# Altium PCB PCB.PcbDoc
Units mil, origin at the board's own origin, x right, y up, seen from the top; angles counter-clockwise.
Board outline 4950 x 3450 mil, 2 copper layers (Top Layer, Bottom Layer), stack 62 mil thick; 23 components, 0 nets, 11 pads, 0 vias.
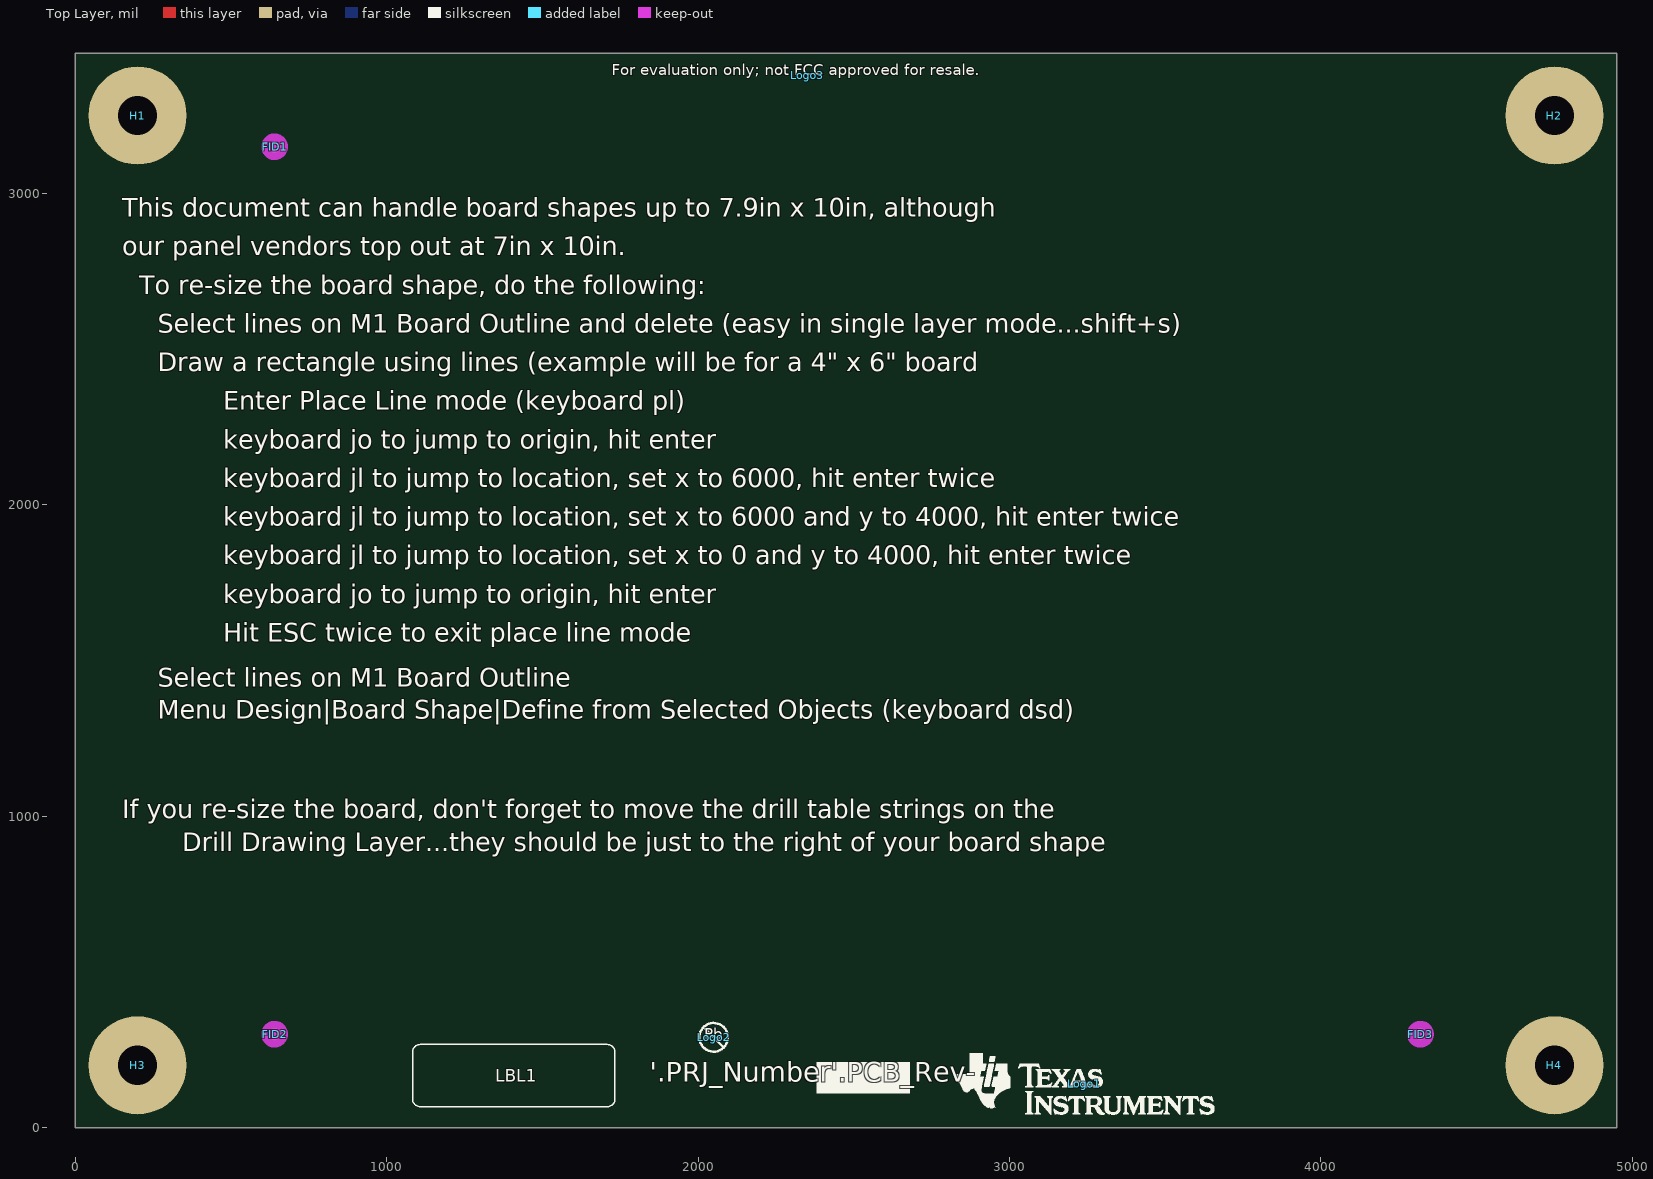
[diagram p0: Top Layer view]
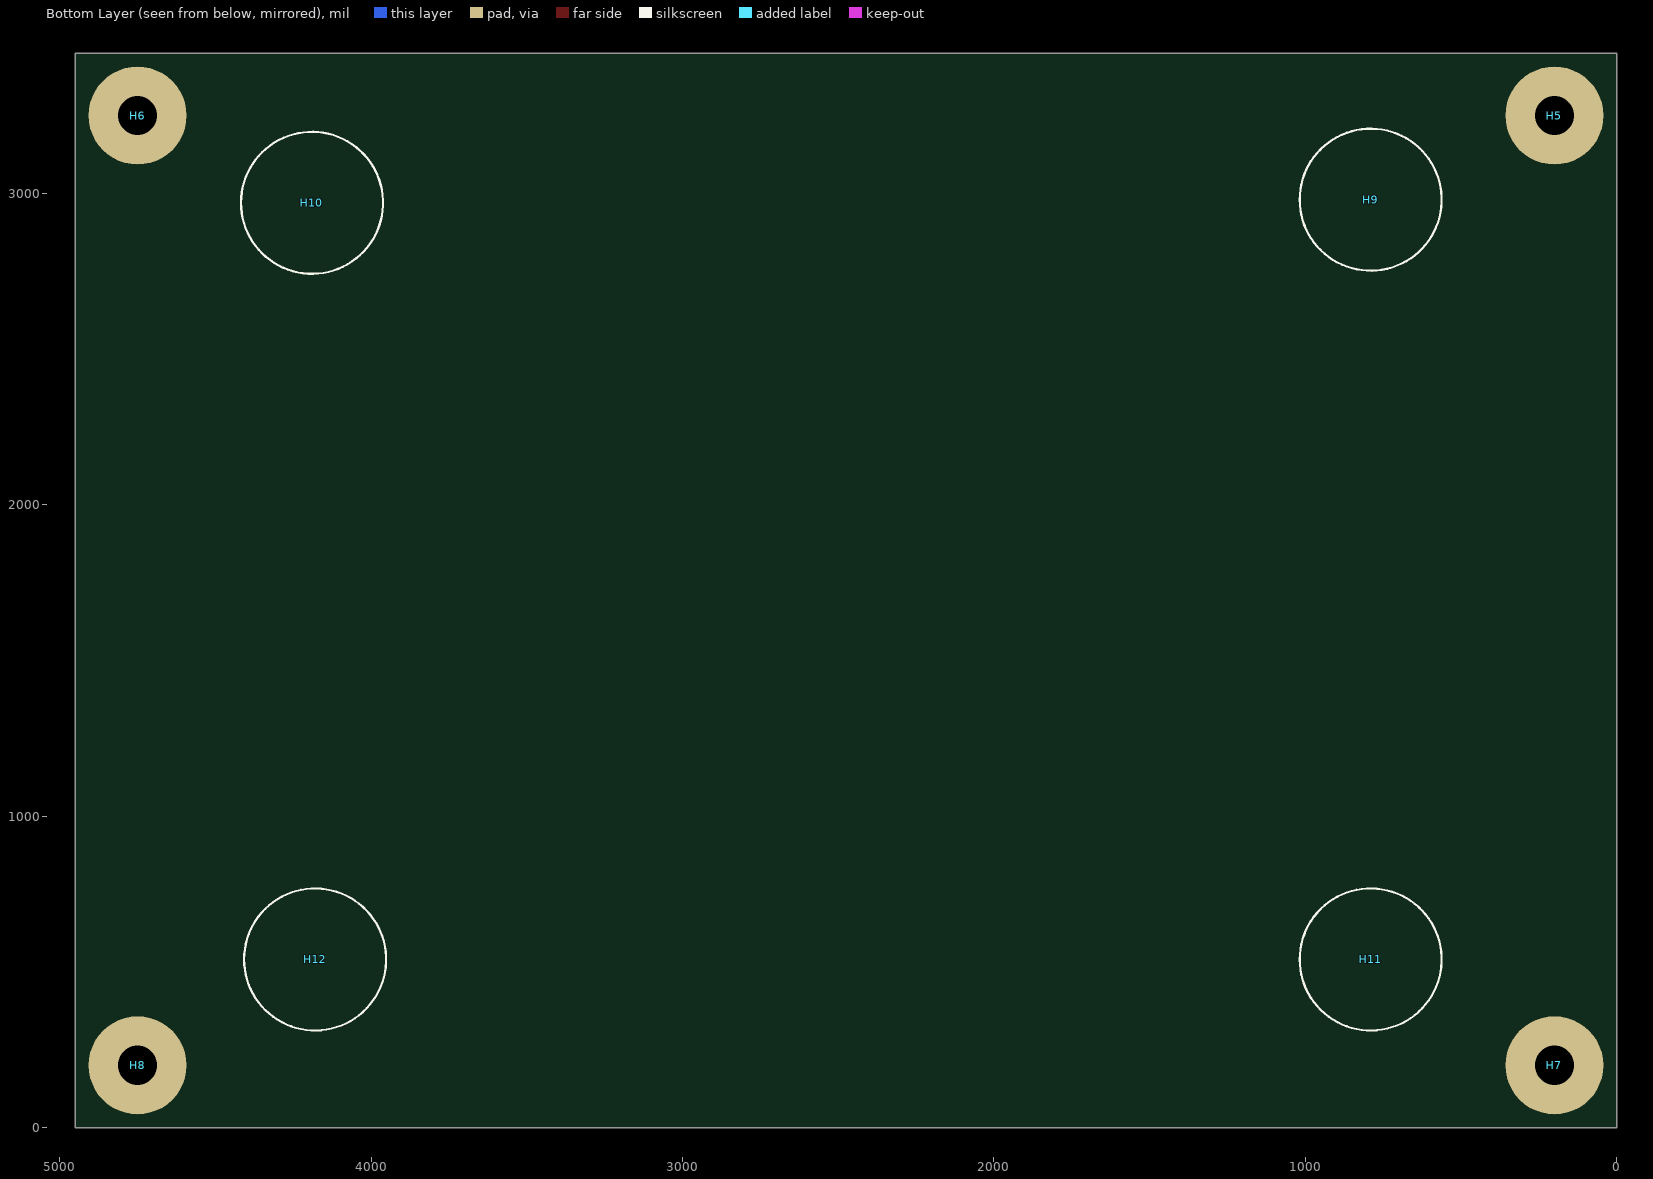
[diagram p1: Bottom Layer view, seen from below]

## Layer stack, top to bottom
Top Solder: solder mask 0.4, Solder Resist, Dk 3.5
Top Layer: signal copper 1.4
Dielectric1: core 59.2, FR-4, Dk 4.8
Bottom Layer: signal copper 1.4
Bottom Solder: solder mask 0.4, Solder Resist, Dk 3.5

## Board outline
0,0 4950,0 4950,3450 0,3450

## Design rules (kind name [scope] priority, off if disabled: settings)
AcuteAngle [All] p1: minimum=4.50000000000000E+0001 checktracksonly=FALSE
AssemblyTestPointUsage [All] p1: valid=2
BoardOutlineClearance BoardOutlineClearance_MountingHoles [OnCopper and InComponentClass('Mounting Holes')] p1: gap=40 ignorepadtopadclearanceinfootprint=FALSE
BoardOutlineClearance BoardOutlineClearance_Poly [OnCopper and IsPoly] p2: gap=25 ignorepadtopadclearanceinfootprint=FALSE
BoardOutlineClearance [OnCopper and Not InComponentClass('Logo') and not InComponentClass('FiducialMark') and not InRegion(1000,500,4000,800) and not InPoly] p3: gap=75 ignorepadtopadclearanceinfootprint=FALSE
Clearance Clearance_Keepouts [((IsTrack Or IsArc) And Not InPoly) And IsFree and IsKeepOut vs ((IsTrack Or IsArc) And Not InPoly) And IsFree and IsKeepOut] p1: gap=0 ignorepadtopadclearanceinfootprint=FALSE
Clearance Clearance_Poly [InPolygon] p2: gap=25 ignorepadtopadclearanceinfootprint=FALSE except(0: Arc-Hole Track-Hole SMDPad-Hole THPad-Hole Via-Hole Fill-Hole Poly-Hole Region-Hole Text-Hole)
Clearance Clearance_FiducialMark [IsKeepOut and InComponentClass('FiducialMark') vs IsPad and InComponentClass('FiducialMark')] p3: gap=0 ignorepadtopadclearanceinfootprint=FALSE
Clearance [All] p4: gap=7.87 ignorepadtopadclearanceinfootprint=FALSE except(0: Arc-Hole Track-Hole SMDPad-Hole THPad-Hole Via-Hole Fill-Hole Poly-Hole Region-Hole Text-Hole)
ComponentClearance ComponentClearance_MountingHoles_FiducialMarks [InComponentClass('Mounting Holes') vs InComponentClass('FiducialMark')] p1: gap=50 collisioncheckmode=3 verticalgap=10 showdistances=FALSE
ComponentClearance ComponentClearance_Shunt [InComponentClass('Header') vs InComponentClass('Shunt')] p2: gap=0 collisioncheckmode=3 verticalgap=0 showdistances=FALSE
ComponentClearance ComponentClearance_Logo [InComponentClass('Logo')] p3: gap=50 collisioncheckmode=3 verticalgap=10 showdistances=FALSE
ComponentClearance ComponentClearance_ScrewToNut [(HasFootprint('NY PMS 440 0025 PH')) vs (HasFootprint('Keystone_1902C'))] p4: gap=5 collisioncheckmode=3 verticalgap=10 showdistances=FALSE
ComponentClearance ComponentClearance_MountingHoles [InComponentClass('Mounting Holes')] p5: gap=250 collisioncheckmode=3 verticalgap=100000 showdistances=FALSE
ComponentClearance ComponentClearance_SmallPassives [HasFootprint('0201*') or HasFootprint('0402*') or HasFootprint('0508') or HasFootprint('0603*') or HasFootprint('0612') or HasFootprint('0805*') or HasFootprint('0815*') or HasFootprint('0830*') or HasFootprint('1206*') or HasFootprint('1210*') or HasFootprint('1808*') or HasFootprint('1812*') or HasFootprint('1825*') or HasFootprint('2010*') or HasFootprint('2220*') or HasFootprint('2225*') or HasFootprint('2512*') or HasFootprint('2728*') or HasFootprint('3518*') vs HasFootprint('0201*') or HasFootprint('0402*') or HasFootprint('0508') or HasFootprint('0603*') or HasFootprint('0612') or HasFootprint('0805*') or HasFootprint('0815*') or HasFootprint('0830*') or HasFootprint('1206*') or HasFootprint('1210*') or HasFootprint('1808*') or HasFootprint('1812*') or HasFootprint('1825*') or HasFootprint('2010*') or HasFootprint('2220*') or HasFootprint('2225*') or HasFootprint('2512*') or HasFootprint('2728*') or HasFootprint('3518*')] p6: gap=14.96 collisioncheckmode=3 verticalgap=10 showdistances=FALSE
ComponentClearance ComponentClearance_THtoSMT [IsThruComponent vs IsSMTComponent] p7: gap=40 collisioncheckmode=3 verticalgap=30 showdistances=FALSE
ComponentClearance ComponentClearance_THtoTH [IsThruComponent vs IsThruComponent] p8: gap=30 collisioncheckmode=3 verticalgap=30 showdistances=FALSE
ComponentClearance [All] p9: gap=30 collisioncheckmode=3 verticalgap=10 showdistances=FALSE
DiffPairsRouting [All] p1: maxlimit=100 minlimit=10 mostfreqgap=10 toplayer_minwidth=15 toplayer_maxwidth=15 toplayer_prefwidth=15 bottomlayer_minwidth=15 bottomlayer_maxwidth=15 bottomlayer_prefwidth=15 maxuncoupledlength=1000
FabricationTestPointUsage TestPointUsage [All] p1: valid=2 allowmultiple=FALSE
FabricationTestpoint Testpoint [All] p1: side=3 testpointundercomponent=TRUE minsize=40 maxsize=100 preferedsize=60 minholesize=0 maxholesize=40 preferedholesize=32 testpointgrid=1 allowsidetop=TRUE allowsidebottom=TRUE usegrid=TRUE gridtolerance=0.01
FanoutControl Fanout_LCC [IsLCC] p1: bgadir=Out bgaviamode=Centered fanoutstyle=Auto fanoutdirection=Alternating viagrid=1 // Fanout_LCC (Default Rule)
FanoutControl Fanout_BGA [IsBGA] p2: bgadir=Out bgaviamode=Centered fanoutstyle=Auto fanoutdirection=Alternating viagrid=1 // Fanout_BGA (Default Rule)
FanoutControl Fanout_Default [All] p4: bgadir=Out bgaviamode=Centered fanoutstyle=Auto fanoutdirection=Alternating viagrid=1 // Fanout_Default (Default Rule)
FanoutControl Fanout_Small [(CompPinCount < 5)] p5: bgadir=Out bgaviamode=Centered fanoutstyle=Auto fanoutdirection=OutThenIn viagrid=1 // Fanout_Small (Default Rule)
HoleSize [All] p1: absolutevalues=TRUE maxlimit=251 minlimit=7.87 maxpercent=80.000 minpercent=20.000
MinimumAnnularRing MinimumAnnularRing_ThermalPadVias [IsVia and InAnyComponent] p1: minimumring=5.91
MinimumAnnularRing [All] p2: minimumring=8
MinimumSolderMaskSliver MinimumSolderMaskSliver_Logo [InComponentClass('Logo') vs InComponentClass('Logo')] p1: minsoldermaskwidth=0.7
MinimumSolderMaskSliver [All] p2: minsoldermaskwidth=3.94
PlaneConnect [All] p1: planeconnectstyle=Relief reliefexpansion=10 reliefentries=4 reliefconductorwidth=10 reliefairgap=10
PolygonConnect [All] p1: connectstyle=Relief reliefconductorwidth=10 reliefentries=4 polygonreliefangle="90 Angle" airgapwidth=10
RoutingVias ThermalPadVias [IsVia and InAnyComponent] p1: holewidth=7.87 width=19.68 viastyle="Through Hole" minholewidth=7.87 minwidth=19.68 maxholewidth=12.99 maxwidth=23.62
RoutingVias [All] p2: holewidth=16 width=34 viastyle="Through Hole" minholewidth=7.87 minwidth=26 maxholewidth=40 maxwidth=65
SilkToBoardRegionClearance [Not ((IsComment or IsDesignator) And (Hide <> 'False')) and not InRegion(1000,500,4000,800)] p1:
SilkToSilkClearance SilkToSilkClearance_Pb-FreeLogo [(HasFootprint('Pb-Free_Overlay_Medium') OR HasFootprint('Pb-Free_Overlay_Small')) vs (HasFootprint('Pb-Free_Overlay_Medium') OR HasFootprint('Pb-Free_Overlay_Small'))] p1: silktosilkclearance=0
SilkToSilkClearance [All] p2: silktosilkclearance=4
SilkToSolderMaskClearance SilkToComponentPadClearance [(IsPad or IsFill or IsRegion) and InAnycomponent] p1: minsilkscreentomaskgap=5 clearancetoexposedcopper=TRUE
SilkToSolderMaskClearance "Silk to Solder Mask Opening" [All] p2: minsilkscreentomaskgap=4 clearancetoexposedcopper=FALSE
SolderMaskExpansion [All] p1: expansion=1.97
Width [All] p1: maxlimit=100 minlimit=6 preferedwidth=10 checkconnectedcopper=TRUE
15 further rules are at their usual default settings.

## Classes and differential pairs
component class Label: LBL1
component class AssemblyNote: ZZ1 ZZ2 ZZ3 ZZ4
component class FiducialMark: FID1 FID2 FID3
component class Logo: Logo1
component class "Mounting Holes": H1 H2 H3 H4

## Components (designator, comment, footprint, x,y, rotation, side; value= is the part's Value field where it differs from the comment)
FID1 "Fiducial" Fiducial10-20 640,3150 r0 top
FID2 "Fiducial" Fiducial10-20 640,300 r0 top
FID3 "Fiducial" Fiducial10-20 4320,300 r0 top
H1 "NY PMS 440 0025 PH" "NY PMS 440 0025 PH" 200,3250 r0 top locked
H2 "NY PMS 440 0025 PH" "NY PMS 440 0025 PH" 4750,3250 r0 top locked
H3 "NY PMS 440 0025 PH" "NY PMS 440 0025 PH" 200,200 r0 top locked
H4 "NY PMS 440 0025 PH" "NY PMS 440 0025 PH" 4750,200 r0 top locked
H5 "1902C" Keystone_1902C 200,3250 r180 bottom locked
H6 "1902C" Keystone_1902C 4750,3250 r180 bottom locked
H7 "1902C" Keystone_1902C 200,200 r180 bottom locked
H8 "1902C" Keystone_1902C 4750,200 r180 bottom locked
H9 "SJ-5303 (CLEAR)" Bumpon_SJ5003Transparent 790,2980 r180 bottom
H10 "SJ-5303 (CLEAR)" Bumpon_SJ5003Transparent 4190,2970 r180 bottom
H11 "SJ-5303 (CLEAR)" Bumpon_SJ5003Transparent 790,540 r180 bottom
H12 "SJ-5303 (CLEAR)" Bumpon_SJ5003Transparent 4180,540 r180 bottom
LBL1 "Size: 0.65\" x 0.20 \"" Label_650x200 1408,167 r0 top
Logo1 "Texas Instruments" TI_Stacked_Overlay_Small 3240,140 r0 top
Logo2 "Pb-Free Symbol" Pb-Free_Overlay_Small 2050,290 r0 top
Logo3 "FCC disclaimer" FCC_disclaimer 2350,3380 r0 top
ZZ1 "This Assembly Note is for PCB labels only" AssemblyNoteLabel 185,3938 r0 top
ZZ2 "These assemblies are ESD sensitive, ESD precautions shall be observed." AssemblyNote 185,3829.11 r0 top
ZZ3 "These assemblies must be clean and free from flux and all contaminants. Use of no clean flux is not acceptable." AssemblyNote 185,3740.56 r0 top
ZZ4 "These assemblies must comply with workmanship standards IPC-A-610 Class 2, unless otherwise specified." AssemblyNote 185,3652 r0 top

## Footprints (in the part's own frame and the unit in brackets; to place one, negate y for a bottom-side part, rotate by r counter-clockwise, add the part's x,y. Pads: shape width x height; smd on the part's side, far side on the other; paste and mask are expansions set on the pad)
AssemblyNote [mil] "Assembly Note"
AssemblyNoteLabel [mil] "Assembly Note for PCB Labels"
Bumpon_SJ5003Transparent [mil] "3M Hemispherical Bumpon transparent"
  round 1 on Mech4: 0(0,0)
  silkscreen extent -228,-228 228,228, body extent -219,-219 219,219, height 197
FCC_disclaimer [mil]
Fiducial10-20 [mm]
  round 1 smd mask+0.5: 1(0,0)
  Top Layer keep-out circle w1.178: c0,0 r0.5
Keystone_1902C [mil] "Hex Standoff, 4-40 threaded, nylon"
  body extent -145,-126 146,126, height 501
Label_650x200 [mil] "Thermal Transfer Label"
  silkscreen extent -325,-100 325,100, body extent -325,-100 325,100, height 1
"NY PMS 440 0025 PH" [mm] "4-40 nylon screw and mounting hole"
  round 8 hole 3.2: 1(0,0)
  body extent -3.3,-3.3 3.3,3.3, height 2.69
Pb-Free_Overlay_Small [mil]
  silkscreen extent -46,-46 46,46
TI_Stacked_Overlay_Small [mil]
  silkscreen extent -418,-98 418,98

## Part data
FID1 FID2 FID3: "Fiducial mark.  There is nothing to buy or mount.", Manufacturer=N/A
H1 H2 H3 H4: "Machine Screw, Round, #4-40 x 1/4, Nylon, Philips panhead", DigiKeyPartNumber=H542-ND, Manufacturer="B&F Fastener Supply"
H5 H6 H7 H8: "Standoff, Hex, 0.5\"L #4-40 Nylon", Manufacturer=Keystone, Supplier Part Number 1=36-1902C-ND
H9 H10 H11 H12: "Bumpon, Hemisphere, 0.44 X 0.20, Clear", Manufacturer=3M, Supplier Part Number 1=SJ5303-7-ND
LBL1: library part THT-14-423-10, "Thermal Transfer Printable Labels, 0.650\" W x 0.200\" H - 10,000 per roll", Manufacturer=Brady, Supplier Part Number 1=97C5133
Logo1: library part TI_Logo, "Texas Instrument Corporate Signature"
Logo2: library part Pb-Free
Logo3: library part FCC_disclaimer, "FCC_disclaimer"
ZZ1: library part AssemblyNoteLabel
ZZ2 ZZ3 ZZ4: library part AssemblyNote

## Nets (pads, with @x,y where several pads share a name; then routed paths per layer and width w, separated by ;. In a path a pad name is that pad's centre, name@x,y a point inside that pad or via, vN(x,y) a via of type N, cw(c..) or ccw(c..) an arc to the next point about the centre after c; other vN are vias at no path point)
pads on no net: FID1.1 FID2.1 FID3.1 H1.1 H2.1 H3.1 H4.1 H9.0 H10.0 H11.0 H12.0

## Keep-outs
Keep-Out Layer:
  text ".Layer_Name" at 577,-858.49 h60

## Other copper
Top Layer:
  text ".Layer_Name" at 577,-858.49 h60
Bottom Layer:
  text ".Layer_Name" at 577,-858.49 h60

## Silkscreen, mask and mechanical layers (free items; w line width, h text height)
Top Overlay:
  region: 2680,210 2380,210 2380,110 2680,110
  text "This document can handle board shapes up to 7.9in x 10in, although" at 150,2925 h60
  text "our panel vendors top out at 7in x 10in." at 150,2800.94 h60
  text "To re-size the board shape, do the following:" at 205,2676.88 h60
  text "Select lines on M1 Board Outline and delete (easy in single layer mode...shift+s)" at 265,2552.82 h60
  text "Draw a rectangle using lines (example will be for a 4\" x 6\" board" at 265,2428.76 h60
  text "Enter Place Line mode (keyboard pl)" at 475,2304.71 h60
  text "keyboard jo to jump to origin, hit enter" at 475,2180.65 h60
  text "keyboard jl to jump to location, set x to 6000, hit enter twice" at 475,2056.59 h60
  text "keyboard jl to jump to location, set x to 6000 and y to 4000, hit enter twice" at 475,1932.53 h60
  text "keyboard jl to jump to location, set x to 0 and y to 4000, hit enter twice" at 475,1808.47 h60
  text "keyboard jo to jump to origin, hit enter" at 475,1684.41 h60
  text "Hit ESC twice to exit place line mode" at 475,1560.35 h60
  text "Select lines on M1 Board Outline" at 265,1416.3 h60
  text "Menu Design|Board Shape|Define from Selected Objects (keyboard dsd)" at 265,1312.24 h60
  text "If you re-size the board, don't forget to move the drill table strings on the" at 150,993 h60
  text "Drill Drawing Layer...they should be just to the right of your board shape" at 343,887 h60
  text "'.PRJ_Number'.PCB_Rev-" at 1845,125.77 h108.27
  text ".Layer_Name" at 577,-858.49 h60
Bottom Overlay:
  text ".Layer_Name" at 577,-858.49 h60
Top Paste:
  text ".Layer_Name" at 577,-858.49 h60
Bottom Paste:
  text ".Layer_Name" at 577,-858.49 h60
Top Solder:
  text ".Layer_Name" at 577,-858.49 h60
  text ".Layer_Name" at 577,-858.49 h60
Bottom Solder:
  text ".Layer_Name" at 577,-858.49 h60
Drill Guide:
  text ".Layer_Name" at 577,-858.49 h60
M1 Board Outline:
  the board outline again, w10
  text ".Layer_Name" at 577,-858.49 h60
M2 Board Dimensions:
  rectangle: 125,-400 500,-275
  rectangle: 0,-275 125,-150
  lines w7: 0,-275 1000,-275 ; 125,-400 125,-150 ; 250,-400 250,-150 ; 500,-400 500,-150 ; 750,-400 750,-150 ; 0,-400 0,-150 1000,-150 1000,-400 0,-400
  text ".Layer_Name" at 577,-858.49 h60
M3 3D STEP Top:
  text ".Layer_Name" at 577,-858.49 h60
M4 3D STEP Bottom:
  text ".Layer_Name" at 577,-858.49 h60
M5 Assembly Top:
  lines w10: -292,-930.17 6308,-930.17 ; -292,-726.83 6310,-726.83 ; -292,-523.5 -292,-1133.5 3713,-1133.5 6310,-1133.5 6310,-523.5 -291.5,-523.5 -291.5,-1133.5 1284,-1133.5 ; 2173,-1133.5 2173,-523.5 ; 3440,-726.83 3440,-523.5 ; 4280,-726.83 4280,-523.5 ; 4902,-1140 4902,-937.17
  text "COMPONENTS MARKED 'DNP' SHOULD NOT BE POPULATED." at 1153.5,-318.5 h60
  text "ASSEMBLY VARIANT:" at 1153,-434 h60
  text ".VariantName" at 2189,-434 h60
  text "PCB VIEWED FROM TOP SIDE" at -228.5,-655.67 h60
  text "BOARD #:" at 2248,-655.67 h60
  text ".PRJ_Number" at 2793.5,-655.67 h60
  text "REV:" at 3638,-655.67 h60
  text ".PCB_Rev" at 3929.5,-655.67 h60
  text "SVN REV:" at 4476,-655.67 h60
  text ".VersionControl_RevNumber" at 4982,-655.67 h60
  text "TID #:" at 2248,-859 h60
  text ".TID" at 2793.5,-859 h60
  text "PLOT NAME =" at -228.5,-1064.34 h60
  text ".plot_File_Name" at 577,-1064.34 h60
  text "GENERATED    :" at 2250,-1064.34 h60
  text ".Print_Date" at 3119.5,-1064.34 h60
  text ".Print_Time" at 3848.5,-1064.34 h60
  text "TEXAS INSTRUMENTS" at 5113,-1064.34 h60
M6 Assembly Bottom:
  lines w10: -292.5,-727.33 6309.5,-727.33 ; -290.5,-930.67 6309.5,-930.67 ; 1115.5,-1140.5 1115.5,-937.67 ; 1737.5,-727.33 1737.5,-524 ; 2577.5,-727.33 2577.5,-524 ; 3844.5,-1134 3844.5,-524 ; 4733.5,-1134 6309,-1134 6309,-524 -292.5,-524 -292.5,-1134 2304.5,-1134 6309.5,-1134 6309.5,-524
  text "COMPONENTS MARKED 'DNP' SHOULD NOT BE POPULATED." at 6102,-318 h60
  text ".VariantName" at 5058,-434 h60
  text "ASSEMBLY VARIANT:" at 6097,-434 h60
  text ".VersionControl_RevNumber" at 1035.5,-656.17 h60
  text "SVN REV:" at 1541.5,-656.17 h60
  text ".PCB_Rev" at 2088,-656.17 h60
  text "REV:" at 2379.5,-656.17 h60
  text ".PRJ_Number" at 3224,-656.17 h60
  text "BOARD #:" at 3769.5,-656.17 h60
  text "PCB VIEWED FROM BOTTOM SIDE" at 6246,-656.17 h60
  text ".TID" at 3224,-859.5 h60
  text "TID #:" at 3769.5,-859.5 h60
  text "TEXAS INSTRUMENTS" at 904.5,-1064.84 h60
  text ".Print_Time" at 2169,-1064.84 h60
  text ".Print_Date" at 2898,-1064.84 h60
  text "GENERATED    :" at 3767.5,-1064.84 h60
  text ".plot_File_Name" at 5440.5,-1064.84 h60
  text "PLOT NAME =" at 6246,-1064.84 h60
M9 Title Sheet:
  drawing of 57 lines, arcs and shapes, not listed
  text "1" at 739.84,8036.5 h70
  text "2" at 3235.5,8036.5 h70
  text "3" at 5724.84,8036.5 h70
  text "4" at 8231.51,8036.5 h70
  text "5" at 10730.5,8036.5 h70
  text "6" at 13235.5,8036.5 h70
  text "A" at -416.5,6893.5 h70
  text "A" at 14383.5,6893.5 h70
  text "B" at -416.5,4513.5 h70
  text "B" at 14383.5,4513.5 h70
  text "C" at -416.5,2138.5 h70
  text "C" at 14383.5,2138.5 h70
  text "PROJECT TITLE:" at 11343.5,277.5 h45
  text ".PRJ_Title" at 11393.5,144.17 h70
  text "DESIGNED FOR:" at 11343.5,-23.5 h45
  text ".PRJ_Customer" at 11393.5,-163.5 h70
  text "D" at -416.5,-231.5 h70
  text "D" at 14383.5,-231.5 h70
  text "FILE NAME:" at 11343.5,-323.5 h45
  text ".PCB_File_Name_No_Path" at 11393.5,-443.5 h70
  text "Texas Instruments (TI) and/or its licensors do not warrant the accuracy or completeness of this specification" at 6374,-605.34 h45
  text "ENGINEER:" at 11343.5,-613.5 h45
  text "LAYOUT BY:" at 12848.5,-613.5 h45
  text "or any information contained therein. TI and/or its licensors do not warrant that this design will meet" at 6329.01,-718 h45
  text ".PRJ_Engineer" at 11393.5,-768.49 h70
  text ".PCB_Layout" at 12899,-768.49 h70
  text "the specifications, will be suitable for your application or fit for any particular purpose, or will operate in" at 6329.01,-830.67 h45
  text ".Layer_Name" at 577,-858.49 h60
  text "ALTIUM DESIGNER VERSION:" at 12848.5,-923.5 h45
  text "an implementation. TI and/or its licensors do not warrant that the design is production worthy. You should" at 6329.01,-943.33 h45
  text "completely validate and test your design implementation to confirm the system functionality for your application." at 6374,-1056 h45
  text ".print_Scale" at 11393.5,-1056.83 h70
  text ".Application_BuildNumber" at 12899,-1056.83 h70
  text "1" at 739.84,-1263.5 h70
  text "2" at 3235.5,-1263.5 h70
  text "3" at 5724.84,-1263.5 h70
  text "4" at 8231.51,-1263.5 h70
  text "5" at 10730.5,-1263.5 h70
  text "6" at 13235.5,-1263.5 h70
M10 Fab Notes:
  drawing of 189 lines, arcs and shapes, not listed
  text "DESIGN INFORMATION" at 12382.02,6356.17 h60
  text "MIN. TRACK WIDTH:" at 11737.46,6224.05 h60
  text "8" at 12833.7,6224.05 h60
  text "MIL" at 12988.46,6224.05 h60
  text "MIN. CLEARANCE:" at 11737.46,6099.92 h60
  text "0.2" at 12773.7,6099.93 h60
  text "mm" at 12988.46,6099.92 h60
  text "MIN. VIA PAD SIZE:" at 11737.46,5975.8 h60
  text "24" at 12803.71,5975.8 h60
  text "MIL" at 12988.46,5975.8 h60
  text "0.05mm (2MIL)" at 12432.46,5845.9 h60
  text "MINIMUM ANNULAR RING" at 11408.23,5837.67 h60
  text "EXTERNAL" at 13140.46,5837.67 h60
  text "PER" at 11608.23,5727.55 h60
  text "IPC-D-275 CLASS 2 LEVEL C" at 11828.23,5727.54 h60
  text "MIL, HOLES" at 13316.46,5627.07 h60
  text "+/-" at 12924,5618.48 h60
  text "+/-" at 13778,5618.48 h60
  text "REGISTRATION TOLERANCES:" at 11408.23,5617.42 h60
  text "METAL" at 12608,5617.42 h60
  text "5" at 13184.2,5617.42 h60
  text "3" at 14017.2,5617.42 h60
  text "MIL" at 14133.46,5617.42 h60
  text "HOLE SIZE TOLERANCE (UNLESS OTHERWISE SPECIFIED):" at 11408.23,5519.1 h60
  text "+/-" at 13778,5516.23 h60
  text "3" at 14017.2,5515.17 h60
  text "MIL" at 14133.46,5515.17 h60
  text "MATERIAL:" at 11333.46,5377.52 h60
  text "FR-4 High Tg" at 12319.9,5249 h60
  text "X" at 12175.46,5241.01 h60
  text "FR-408" at 11754.46,5236.49 h60
  text "OTHER" at 13242.46,5236.49 h60
  text "62 MIL (1.6mm) +/-10%" at 12074.56,5093.46 h60
  text "X" at 11954.46,5091.01 h60
  text "THICKNESS:" at 11408.23,5085.24 h60
  text "OTHER" at 13359.46,5085.24 h60
  text "TOLERANCE:" at 11408.23,4946.92 h60
  text "X" at 12256.46,4946.92 h60
  text "ANSI IPC-6012 TYPE 3 CLASS 2" at 12434.48,4946.92 h60
  text "OTHER +/-" at 12434.46,4802.73 h60
  text "BOW & TWIST:" at 11408.23,4657.54 h60
  text "X" at 12256.46,4657.54 h60
  text "ANSI IPC-6012 TYPE 3 CLASS 2" at 12434.48,4657.54 h60
  text "OTHER +/-" at 12434.46,4510.85 h60
  text "DRILLING:" at 11333.46,4380.23 h60
  text "NC_DRILL FILES" at 13094.46,4275.04 h60
  text "REFERENCE:" at 11408.23,4271.1 h60
  text "X" at 12065.46,4271.01 h60
  text "AS SHOWN" at 12243.46,4271.1 h60
  text "X" at 12966.46,4271.1 h60
  text "OTHER" at 13392.46,4128.85 h60
  text "PTH COPPER THICKNESS:" at 11407.91,4125.32 h60
  text "X" at 12547.14,4125.32 h60
  text "20-30 um" at 12675.14,4125.32 h60
  text "BOARD FINISH:" at 11333.46,3977.73 h60
  text "SILKSCREEN:" at 11488.68,3867.6 h60
  text "X" at 12446.46,3867.6 h60
  text "TOP" at 12563.46,3867.6 h60
  text "X" at 12956.46,3867.6 h60
  text "BOTTOM" at 13074.46,3867.6 h60
  text "SILKSCREEN COLOR:" at 11488.68,3712.41 h60
  text "X" at 12445.46,3712.41 h60
  text "WHITE" at 12563.46,3712.41 h60
  text "OTHER" at 13074.46,3712.41 h60
  text "X" at 12576.46,3568.96 h60
  text "GREEN" at 12694.46,3568.96 h60
  text "OTHER" at 13312.46,3568.96 h60
  text "SOLDER RESIST COLOR:" at 11488.68,3562.1 h60
  text "X" at 12576.46,3414.71 h60
  text "MATTE" at 12694.46,3414.71 h60
  text "SEMI-GLOSS" at 13312,3414.07 h60
  text "IMMERSION GOLD (ENIG)" at 12394.46,3241.94 h60
  text "ENEPIG" at 13732,3234.72 h60
  text "SURFACE FINISH:" at 11333.46,3233.72 h60
  text "X" at 12216.46,3233.72 h60
  text "IMM. TIN/SILVER OR EQUIV" at 11663,3096.4 h60
  text "OTHER" at 13094.46,3092.47 h60
  text "ARRAY/PANEL:" at 11333.46,2937.09 h60
  text "CUT AND TRIM PER M1 BOARD OUTLINE" at 12394.46,2928.87 h60
  text "N.C. ROUTE" at 12394.46,2792.9 h60
  text "X" at 13082.46,2792.9 h60
  text "V. SCORE" at 13260.46,2792.9 h60
  text "CERTIFICATION:" at 11333.46,2663.77 h60
  text "MATERIALS AND WORKMANSHIP FOR ALL PCBS" at 12058.46,2663.77 h60
  text "TO MEET OR EXCEED THE REQUIREMENTS OF:" at 12058.46,2569.71 h60
  text "X" at 11695.97,2441.08 h60
  text "ANSI IPC-A-600F CLASS ->" at 11823.96,2441.08 h60
  text "X" at 13471.97,2441.08 h60
  text "2" at 13581.96,2441.08 h60
  text "1" at 13266.96,2439.58 h60
  text "3" at 13935.96,2439.58 h60
  text "X" at 12507.97,2293.39 h60
  text "RoHS" at 12635.96,2293.39 h60
  text "OTHER" at 13280.36,2293.39 h60
  text "PER ORDER" at 13677.42,2293.39 h60
  text "ALL BOARDS MUST MEET OR EXCEED UL94-V0 REQUIREMENTS." at 11361,2139.57 h60
  text "PCB MUST BEAR THE UL94V-0 UL REGISTERED MATERIAL ID NUMBER" at 11361,2023.5 h60
  text "ADDITIONAL REQUIREMENTS:" at 11333.46,1854.08 h60
  text "MICROSECTION:" at 11408.23,1746.95 h60
  text "YES" at 12313.96,1746.95 h60
  text "REQUIRED" at 13175.46,1602.62 h60
  text "BARE BOARD ELEC. TEST:" at 11408.23,1599.76 h60
  text "NONE" at 12713.96,1599.76 h60
  text "X" at 13057.46,1599.76 h60
  text "PER ORDER" at 13767.46,1599.76 h60
  text "XX MIL VIAS REQUIRE NON-CONDUCTIVE FILL AND PLANARIZE" at 11576.38,1394.82 h59
  text "XX MIL VIAS REQUIRE CONDUCTIVE FILL AND PLANARIZE" at 11584.38,1290.84 h60
  text "OUTER XX MIL VIAS REQUIRE 50 OHM SINGLE-ENDED IMPEDANCE" at 11583.39,1127.46 h58
  text "LAYER 2 & 3 (INNER LAYERS) XX MIL WIDE, XX MIL SPACE / TRACES REQUIRE 100 OHM DIFFERENTIAL IMPEDANCE" at 11575.39,891.74 h60
  text ".Layer_Name" at 577,-858.49 h60
M11 Gerber Information:
  lines w10: -292,-930.17 6308,-930.17 ; -292,-726.83 6310,-726.83 ; -292,-523.5 -292,-1133.5 3713,-1133.5 6310,-1133.5 6310,-523.5 -291.5,-523.5 -291.5,-1133.5 1284,-1133.5 ; 2173,-1133.5 2173,-523.5 ; 3440,-726.83 3440,-523.5 ; 4280,-726.83 4280,-523.5 ; 4902,-1140 4902,-937.17
  text "ALL ARTWORK VIEWED FROM TOP SIDE" at -228.5,-655.67 h60
  text "BOARD #:" at 2248,-655.67 h60
  text ".PRJ_Number" at 2793.5,-655.67 h60
  text "REV:" at 3638,-655.67 h60
  text ".PCB_Rev" at 3929.5,-655.67 h60
  text "SVN REV:" at 4476,-655.67 h60
  text ".VersionControl_RevNumber" at 4982,-655.67 h60
  text "LAYER NAME =" at -228.5,-858.49 h60
  text "TID #:" at 2248,-859 h60
  text ".TID" at 2793.5,-859 h60
  text "PLOT NAME =" at -228.5,-1064.34 h60
  text ".plot_File_Name" at 577,-1064.34 h60
  text "GENERATED    :" at 2250,-1064.34 h60
  text ".Print_Date" at 3119.5,-1064.34 h60
  text ".Print_Time" at 3848.5,-1064.34 h60
  text "TEXAS INSTRUMENTS" at 5113,-1064.34 h60
M12 Stackup:
  drawing of 191 lines, arcs and shapes, not listed
  text "Layer" at 9790.34,7830 h60
  text "Name" at 10200.26,7830 h60
  text "Material" at 11130,7830 h60
  text "Thickness" at 11989.77,7830 h60
  text "Constant" at 12639.6,7830 h60
  text "Board Layer Stack" at 13209.46,7830 h60
  text "1" at 9790.34,7710 h60
  text "Top Overlay" at 10200.26,7710 h60
  text "2" at 9790.34,7590 h60
  text "Top Solder" at 10200.26,7590 h60
  text "Solder Resist" at 11130,7590 h60
  text "0.40mil" at 11989.77,7590 h60
  text "3.5" at 12639.6,7590 h60
  text "3" at 9790.34,7470 h60
  text "Top Layer" at 10200.26,7470 h60
  text "Copper" at 11130,7470 h60
  text "1.40mil" at 11989.77,7470 h60
  text "4" at 9790.34,7350 h60
  text "Dielectric1" at 10200.26,7350 h60
  text "FR-4" at 11130,7350 h60
  text "59.20mil" at 11989.77,7350 h60
  text "4.8" at 12639.6,7350 h60
  text "5" at 9790.34,7230 h60
  text "Bottom Layer" at 10200.26,7230 h60
  text "Copper" at 11130,7230 h60
  text "1.40mil" at 11989.77,7230 h60
  text "6" at 9790.34,7110 h60
  text "Bottom Solder" at 10200.26,7110 h60
  text "Solder Resist" at 11130,7110 h60
  text "0.40mil" at 11989.77,7110 h60
  text "3.5" at 12639.6,7110 h60
  text "7" at 9790.34,6990 h60
  text "Bottom Overlay" at 10200.26,6990 h60
  text ".Layer_Name" at 577,-858.49 h60
M13 Component Bodies Top:
  text ".Layer_Name" at 577,-858.49 h60
M14 Component Bodies Bottom:
  text ".Layer_Name" at 577,-858.49 h60
M15 Courtyards Top:
  text ".Layer_Name" at 577,-858.49 h60
M16 Courtyards Bottom:
  text ".Layer_Name" at 577,-858.49 h60
Drill Drawing:
  circle w10: c5363.82,3266.02 r27.67
  lines w12: 5286,3201 8518.19,3201 ; 5286,3325.5 8518.19,3325.5 ; 5624.01,3076.5 5624.01,3450 ; 5956.17,3076.5 5956.17,3450 ; 6592.65,3076.5 6592.65,3450 ; 6851.85,3076.5 6851.85,3450 ; 7227.09,3076.5 7227.09,3450 ; 7951.64,3076.5 7951.64,3450 ; 5286,3076.5 8518.19,3076.5 8518.19,3450 5286,3450 5286,3076.5
  text "Symbol" at 5360.7,3362.85 h72
  text "Quantity" at 5661.36,3362.85 h72
  text "Finished Hole Size" at 5993.52,3362.85 h72
  text "Plated" at 6630,3362.85 h72
  text "Hole Type" at 6889.2,3362.85 h72
  text "Drill Layer Pair" at 7264.44,3362.85 h72
  text "Hole Tolerance" at 7988.99,3362.85 h72
  text "4" at 5661.36,3238.35 h60
  text "125.98mil (3.200mm)" at 5993.52,3238.35 h60
  text "PTH" at 6630,3238.35 h60
  text "Round" at 6889.2,3238.35 h60
  text "Top Layer - Bottom Layer" at 7264.44,3238.35 h60
  text "4 Total" at 5661.36,3113.85 h60
  text ".Layer_Name" at 577,-858.49 h60
M17 Embedded Cavity:
  text ".Layer_Name" at 577,-858.49 h60
M18 Embedded Assembly:
  text ".Layer_Name" at 577,-858.49 h60
M19 Embedded Keepout:
  text ".Layer_Name" at 577,-858.49 h60

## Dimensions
0,0 to 4950,0 on M2 Board Dimensions
0,0 to 0,3450 on M2 Board Dimensions
0,-400 to 1000,-400 on M2 Board Dimensions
